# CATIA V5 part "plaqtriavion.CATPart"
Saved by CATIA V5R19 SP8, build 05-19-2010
Part number: plaqtriavion
Bounding box of the stored display mesh (mm): x 40 to 50, y -90 to 11.131, z -110 to 15.99
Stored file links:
  C:\Users\rcousturie\Desktop\EU_thinkMotion\iao\IAO_MMS_Groupe1\flamrini\Lamrini_projet_IAO2011\Lamrini_projet_IAO2011\projet_iao_traindatterrissage\projet_iao_traindatterrissage\plaqtriavion.CATPart
  C:\Users\rcousturie\Desktop\EU_thinkMotion\iao\IAO_MMS_Groupe1\flamrini\Lamrini_projet_IAO2011\Lamrini_projet_IAO2011\projet_iao_traindatterrissage\projet_iao_traindatterrissage\trainavion.CATProduct
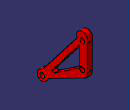
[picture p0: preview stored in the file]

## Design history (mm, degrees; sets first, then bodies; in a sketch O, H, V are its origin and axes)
Set1
  Sketch1 on yz-plane, origin (0, 0, 0), H (0, 1, 0), V (0, 0, 1)
    line L1 (-80, -90) -> (-10, 0)
    point P2 (-10, 0)
    arc A1 centre (0, 5) radius 11.1803 from (-10, 0) to (10, 0) cw
    point P4 (10, 0)
    line L2 (10, 0) -> (10, -50)
    arc A2 centre (-15.9782, -50) radius 25.9782 from (10, -50) to (7.9982, -60) cw
    line L3 (7.9982, -60) -> (-70, -100)
    arc A3 centre (-80, -100) radius 10 from (-70, -100) to (-80, -90) cw
    point P9 (-80, -100)
    line L4 (-60, -80) -> (-5.5556, -10)
    line L5 (-5.5556, -10) -> (-5.5556, -50)
    line L6 (-5.5556, -50) -> (-55.4691, -83.524)
    arc A4 centre (-57.1539, -81.0155) radius 3.0218 from (-55.4691, -83.524) to (-60, -80) cw
    coincidence: P2 H, P4 H, L6 P9
    vertical: L2 V, L5 V
    tangency: A2 L1, A2 L2, A4 L6
    parallelism: L4 L1
Set2
  Line1 "axepivotri/bati": linked copy from another document
  Line2 "axepivotri/tige": linked copy from another document
  Line3 "axepivotri/bras": linked copy from another document
Body1 (main body)
  Pad1: profile Sketch1, direction (1, 0, 0), length 50, opposite side length -40
  Sketch2 on end face of Pad1, origin (50, 0, 0), H (0, 1, 0), V (0, 0, 1)
    point P1 (0, 0)
  Hole1: placed by Sketch2, at (50, 0, 0) direction (-1, 0, 0), diameter 10, up to start face of Pad1
  Sketch3 on end face of Pad1, origin (50, 0, -50), H (0, 1, 0), V (0, 0, 1)
    point P1 (0, 0)
  Hole2: placed by Sketch3, at (50, 0, -50) direction (-1, 0, 0), diameter 10, up to start face of Pad1
  Sketch4 on end face of Pad1, origin (50, -80, -100), H (0, 1, 0), V (0, 0, 1)
    point P1 (0, 0)
  Hole3: placed by Sketch4, at (50, -80, -100) direction (-1, 0, 0), diameter 10, up to start face of Pad1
